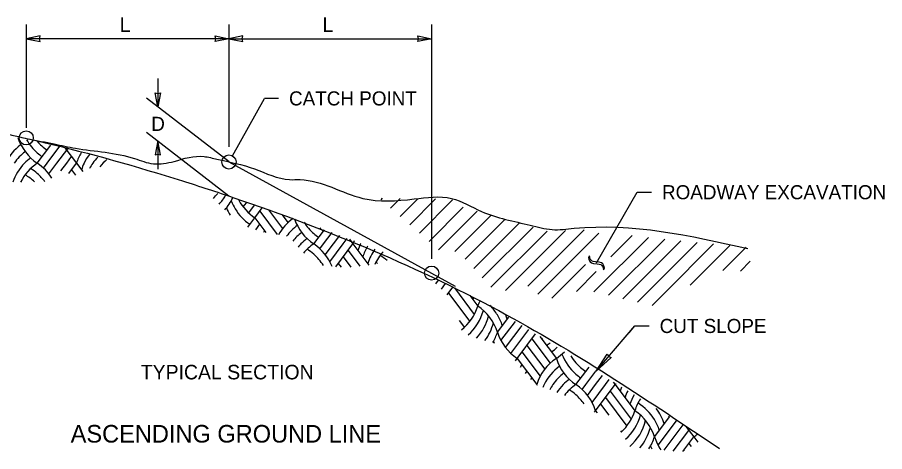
# Model space of a CAD drawing. Extents: x 99862 to 103151, y 100000 to 102076.
# Drawn here: x 100486 to 101470, y 100820 to 101313 of the extents above; entities that cross this region are included whole.
import ezdxf

# ---------------------------------------------------------------- set-up
doc = ezdxf.new("R2010")
doc.units = 0
for name, color, linetype in [('Level 1', 7, 'Continuous'), ('Level 14', 7, 'Continuous'), ('Level 15', 7, 'Continuous'), ('Level 16', 7, 'Continuous'), ('Level 17', 7, 'Continuous'), ('Level 20', 7, 'Continuous'), ('Level 4', 7, 'Continuous')]:
    doc.layers.add(name, color=color, linetype=linetype)

msp = doc.modelspace()

# ---------------------------------------------------------------- linework, layer by layer
at = {"layer": 'Level 1'}
msp.add_spline([(100494.64, 101176.21), (100515.6, 101171.36), (100672.98, 101127.68), (100731.37, 101108.58), (101041.15, 100975.34), (101282.62, 100823.72)], degree=3, dxfattribs=at)
at = {"layer": 'Level 14'}
msp.add_circle((100495.8, 101176.56), 8, dxfattribs=at)
at = {"layer": 'Level 15'}
for p, q in [((100495.8, 101305.14), (100495.8, 101187.96)), ((100725.8, 101305.14), (100725.8, 101166.48)), ((100955.79, 101305.14), (100955.79, 101039.01)), ((100725.8, 101289.14), (100495.8, 101289.14)), ((100725.8, 101289.14), (100955.79, 101289.14)), ((100645.05, 101243.91), (100645.05, 101211.91)), ((100726.14, 101149.17), (100632.39, 101221.7)), ((100729.69, 101156.12), (100766, 101221.34)), ((100782, 101221.34), (100766, 101221.34)), ((100725.8, 101110.52), (100632.39, 101182.78)), ((100645.05, 101172.99), (100645.05, 101140.99)), ((101142.86, 101034.59), (101189.18, 101114.83)), ((101189.19, 101114.83), (101205.19, 101114.83)), ((101142.51, 100911.7), (101186.53, 100962.97)), ((101179.9, 100955.25), (101186.53, 100962.97)), ((101186.53, 100962.97), (101202.53, 100962.97))]:
    msp.add_line(p, q, dxfattribs=at)
for points in [[(100495.8, 101289.14), (100511.53, 101286.05), (100510.8, 101289.14), (100511.53, 101292.22)], [(100725.8, 101289.14), (100710.07, 101286.05), (100710.8, 101289.14), (100710.07, 101292.22)], [(100725.8, 101289.14), (100741.52, 101286.05), (100740.79, 101289.14), (100741.52, 101292.22)], [(100955.79, 101289.14), (100940.07, 101286.05), (100940.8, 101289.14), (100940.07, 101292.22)], [(100645.05, 101211.91), (100641.96, 101227.63), (100645.05, 101226.9), (100648.13, 101227.63)], [(100645.05, 101172.99), (100641.96, 101157.27), (100645.05, 101158), (100648.13, 101157.27)], [(101142.51, 100911.7), (101155.11, 100930.96), (101156.69, 100928.22), (101159.64, 100927.07)]]:
    msp.add_lwpolyline(points, close=True, dxfattribs=at)
for centre in [(100725.8, 101149.14), (100955.79, 101023.01)]:
    msp.add_circle(centre, 8, dxfattribs=at)
at = {"layer": 'Level 16'}
msp.add_line((100725.8, 101149.14), (100982.62, 101008.14), dxfattribs=at)
for points in [[(100081.27, 101269.43), (100433.79, 101190.08), (100494.64, 101176.21)], [(100498.16, 101175.4), (100527.39, 101169.63), (100551.65, 101164.77), (100618.73, 101153.13), (100640.02, 101147.1), (100663.49, 101149.72)], [(100663.49, 101149.72), (100697.52, 101155.38), (100712.23, 101152.2)], [(100712.23, 101152.2), (100754.97, 101141.2), (100794.68, 101129.14), (100806.74, 101129.14), (100877.66, 101107.87), (100935.81, 101107.16), (100978.36, 101107.87), (101012.4, 101092.97), (101067.72, 101077.37), (101092.54, 101072.41), (101117.36, 101073.82), (101314.66, 101050.76)]]:
    msp.add_spline(points, degree=3, dxfattribs=at)
at = {"layer": 'Level 17'}
for p, q in [((100898.35, 101106.27), (100900.03, 101107.95)), ((100909.24, 101096.8), (100920.13, 101107.68)), ((100909.24, 101096.8), (100920.13, 101107.68)), ((100920.14, 101087.33), (100940.23, 101107.42)), ((100931.03, 101077.85), (100960.33, 101107.15)), ((100941.92, 101068.38), (100979.58, 101106.04)), ((100941.92, 101068.38), (100979.58, 101106.04)), ((100952.81, 101058.91), (100991.76, 101097.85)), ((100963.71, 101049.44), (101007.6, 101093.33)), ((100982.29, 101047.66), (101023.44, 101088.8)), ((100982.29, 101047.66), (101023.44, 101088.8)), ((100993.81, 101038.81), (101039.27, 101084.28)), ((101003.52, 101028.16), (101055.11, 101079.75)), ((101013.23, 101017.5), (101070.95, 101075.23)), ((101013.23, 101017.5), (101070.95, 101075.23)), ((101022.94, 101006.84), (101086.79, 101070.7)), ((101039.59, 101003.13), (101107.79, 101071.33)), ((101064.81, 101007.99), (101128.89, 101072.07)), ((101064.81, 101007.99), (101128.89, 101072.07)), ((101076.12, 100998.94), (101145.4, 101068.22)), ((101159.28, 101041.36), (101183.47, 101065.55)), ((101139.96, 101001.68), (101201.71, 101063.43)), ((101156.44, 100997.8), (101220.23, 101061.58)), ((101172.93, 100993.92), (101238.74, 101059.73)), ((101172.93, 100993.92), (101238.74, 101059.73)), ((101189.41, 100990.04), (101257.25, 101057.88)), ((101219.65, 100999.91), (101275.77, 101056.03)), ((101249.22, 101009.12), (101294.28, 101054.18)), ((101266.61, 101026.51), (101294.28, 101054.18)), ((101286.35, 101025.88), (101312.79, 101052.32)), ((101306.09, 101025.26), (101317.22, 101036.39)), ((101092.26, 100994.71), (101130.23, 101032.68)), ((101120.09, 101002.18), (101142.64, 101024.72)), ((101205.9, 100986.16), (101219.5, 100999.76))]:
    msp.add_line(p, q, dxfattribs=at)
at = {"layer": 'Level 20'}
for p, q in [((101134.86, 101042.5), (101133.81, 101040.67)), ((101133.81, 101040.67), (101134.17, 101038.55)), ((101134.17, 101038.55), (101134.81, 101036.9)), ((101134.81, 101036.9), (101135.77, 101035.59)), ((101135.85, 101038.94), (101134.86, 101042.5)), ((101135.77, 101035.59), (101137.09, 101034.59)), ((101136.72, 101037.54), (101135.85, 101038.94)), ((101137.8, 101036.62), (101136.72, 101037.54)), ((101137.09, 101034.59), (101139.39, 101033.7)), ((101139.21, 101036.09), (101137.8, 101036.62)), ((101141.62, 101035.89), (101139.21, 101036.09)), ((101146.02, 101035.51), (101141.62, 101035.89)), ((101148.57, 101034.58), (101146.02, 101035.51)), ((101149.97, 101033.51), (101148.57, 101034.58)), ((101139.39, 101033.7), (101143.47, 101033.43)), ((101143.47, 101033.43), (101146.02, 101033.21)), ((101146.02, 101033.21), (101147.83, 101032.57)), ((101147.83, 101032.57), (101148.88, 101031.75)), ((101148.88, 101031.75), (101149.68, 101030.65)), ((101149.68, 101030.65), (101150.3, 101029.03)), ((101150.99, 101032.14), (101149.97, 101033.51)), ((101150.3, 101029.03), (101150.82, 101026.66)), ((101150.82, 101026.66), (101151.88, 101028.49)), ((101151.62, 101030.47), (101150.99, 101032.14)), ((101151.88, 101028.49), (101151.62, 101030.47))]:
    msp.add_line(p, q, dxfattribs=at)
at = {"layer": 'Level 4'}
for p, q in [((100508.31, 101147.82), (100523.75, 101168.4)), ((100519.44, 101147.82), (100533.78, 101166.93)), ((100530.58, 101147.82), (100542.88, 101164.22)), ((100539.75, 101165.29), (100552.86, 101147.82)), ((100541.72, 101147.82), (100547.29, 101155.24)), ((100515.29, 101142.28), (100519.44, 101147.82)), ((100521.4, 101135.58), (100530.58, 101147.82)), ((100535.15, 101139.06), (100541.72, 101147.82)), ((100544.06, 101136.09), (100552.86, 101147.82)), ((100552.86, 101147.82), (100560.06, 101138.22)), ((100547.29, 101140.39), (100551.85, 101134.31)), ((100742.09, 101098.05), (100745.56, 101102.69)), ((100748.2, 101091.36), (100754.77, 101100.11)), ((100755.19, 101085.82), (100763.52, 101096.93)), ((100770.84, 101094.65), (100786.64, 101073.58)), ((100747.15, 101075.1), (100755.19, 101085.82)), ((100755.19, 101085.82), (100767.76, 101069.05)), ((100760.75, 101093.24), (100780.59, 101066.79)), ((100786.19, 101089.02), (100792.75, 101080.28)), ((100756.17, 101072.28), (100760.75, 101078.39)), ((100765.22, 101069.5), (100766.32, 101070.97)), ((100822.01, 101056.12), (100834.11, 101072.26)), ((100833.14, 101056.12), (100842.84, 101069.05)), ((100844.28, 101056.12), (100851.5, 101065.75)), ((100828.99, 101050.58), (100833.14, 101056.12)), ((100835.1, 101043.88), (100844.28, 101056.12)), ((100840.27, 101035.92), (100855.42, 101056.12)), ((100847.11, 101030.19), (100866.55, 101056.12)), ((100855.42, 101056.12), (100860.13, 101062.4)), ((100862.55, 101061.46), (100866.55, 101056.12)), ((100866.55, 101056.12), (100884.68, 101031.96)), ((100860.99, 101048.69), (100874.32, 101030.92)), ((100855.42, 101041.27), (100863.96, 101029.88)), ((100849.85, 101033.84), (100853.01, 101029.63)), ((100960.38, 101010.82), (100963.5, 101014.97)), ((100966.89, 101004.65), (100971.65, 101010.99)), ((100973.39, 100998.47), (100979.8, 101007.01)), ((100981.6, 101006.13), (101004.2, 100976)), ((100974.8, 101000.35), (100999.03, 100968.04)), ((100999.17, 100997.55), (101008.21, 100985.5)), ((100987.07, 100969.14), (100992.92, 100961.34)), ((101030.48, 100955.8), (101043.33, 100972.94)), ((101034.5, 100946.3), (101050.93, 100968.22)), ((101039.66, 100938.34), (101058.53, 100963.5)), ((101045.78, 100931.64), (101066.13, 100958.78)), ((101052.76, 100926.1), (101073.72, 100954.06)), ((101069.46, 100948.38), (101090.32, 100920.56)), ((101078.62, 100951.01), (101097.31, 100926.1)), ((101063.89, 100940.95), (101084.21, 100913.87)), ((101058.33, 100933.53), (101079.04, 100905.91)), ((101050.78, 100923.46), (101052.76, 100926.1)), ((101052.76, 100926.1), (101075.03, 100896.41)), ((101056.5, 100916.25), (101058.33, 100918.68)), ((101062.22, 100909.03), (101063.89, 100911.25)), ((101119.58, 100896.41), (101134.5, 100916.31)), ((101130.71, 100896.41), (101142.11, 100911.6)), ((101141.85, 100896.41), (101149.72, 100906.89)), ((101068.24, 100902.2), (101069.46, 100903.83)), ((101152.99, 100896.41), (101157.32, 100902.18)), ((101161.94, 100899.32), (101164.13, 100896.41)), ((101074.74, 100896.02), (101075.03, 100896.41)), ((101075.03, 100896.41), (101075.56, 100895.71)), ((101126.56, 100890.86), (101130.71, 100896.41)), ((101132.67, 100884.17), (101141.85, 100896.41)), ((101137.84, 100876.21), (101152.99, 100896.41)), ((101141.85, 100866.71), (101164.13, 100896.41)), ((101158.56, 100888.98), (101182.39, 100857.21)), ((101164.13, 100896.41), (101186.4, 100866.71)), ((101152.99, 100881.56), (101177.22, 100849.24)), ((101147.42, 100874.13), (101156.71, 100861.74)), ((101140.55, 100864.97), (101141.85, 100866.71)), ((101141.85, 100866.71), (101143.61, 100864.36)), ((101208.67, 100837.01), (101225.94, 100860.03)), ((101212.68, 100827.51), (101233.6, 100855.4)), ((101219.61, 100821.89), (101241.26, 100850.76)), ((101244.27, 100848.94), (101253.22, 100837.01)), ((101170.08, 100843.92), (101171.11, 100842.55)), ((101229.95, 100820.84), (101247.65, 100844.43)), ((101240.65, 100820.24), (101253.22, 100837.01)), ((101247.65, 100829.58), (101250.21, 100826.18)), ((101253.22, 100837.01), (101257.81, 100830.89)), ((101242.08, 100822.16), (101242.61, 100821.46))]:
    msp.add_line(p, q, dxfattribs=at)
for centre, start, end in [((100539.75, 101194.6), 198.22662, 236.09639), ((100539.75, 101194.6), 202.24668, 203.08162), ((100545.32, 101202.02), 209.35448, 228.95992), ((100550.89, 101209.45), 220.5204, 236.09639), ((100523.04, 101123.31), 126.71786, 154.2266), ((100528.61, 101115.88), 127.1006, 145.49109), ((100534.18, 101108.46), 126.331, 135.71278), ((100545.32, 101202.02), 228.95986, 236.09639), ((100606.57, 101130.73), 149.28802, 162.3566), ((100612.14, 101123.31), 141.90599, 154.2266), ((100617.71, 101115.88), 136.41204, 145.49109), ((100534.18, 101108.46), 135.71269, 161.79649), ((100539.75, 101101.03), 123.90361, 153.45584), ((100476.87, 101101.03), 31.64966, 56.09634), ((100612.14, 101123.31), 154.22654, 162.3566), ((100617.71, 101115.88), 145.49102, 152.80365), ((100623.28, 101108.46), 129.59897, 141.21541), ((100623.28, 101108.46), 134.50839, 135.71278), ((100465.73, 101086.18), 45.67354, 59.30215), ((100471.3, 101093.61), 48.95968, 58.54646), ((100471.3, 101093.61), 35.97372, 48.95975), ((100460.16, 101078.76), 57.39834, 58.48737), ((100668.06, 101147.45), 315.29494, 323.03736), ((100673.63, 101140.02), 316.62931, 328.95774), ((100679.2, 101132.6), 317.96456, 334.509), ((100781.06, 101125.18), 201.08053, 211.33197), ((100786.63, 101132.6), 208.28144, 236.09639), ((100775.49, 101117.75), 201.43438, 210.92517), ((100781.06, 101125.18), 211.33188, 236.09639), ((100831.17, 101039.03), 125.39128, 150.78643), ((100853.45, 101102.9), 199.11695, 236.09639), ((100836.74, 101031.61), 126.30625, 143.79192), ((100859.02, 101110.33), 211.65684, 228.95992), ((100864.58, 101117.75), 230.55849, 236.09639), ((100842.31, 101024.19), 127.1006, 141.55728), ((100859.02, 101110.33), 228.95986, 236.09639), ((100847.88, 101016.76), 135.71269, 140.73228), ((100847.88, 101016.76), 126.331, 135.71278), ((100853.45, 101009.34), 123.90361, 139.90917), ((100790.57, 101009.34), 22.16876, 56.09634), ((100920.27, 101039.03), 158.77108, 162.3566), ((100925.84, 101031.61), 154.22654, 162.3566), ((100925.84, 101031.61), 153.78062, 154.2266), ((100785, 101001.91), 48.95968, 58.54646), ((100785, 101001.91), 31.71162, 48.95975), ((100931.41, 101024.19), 148.7928, 162.3566), ((100936.97, 101016.76), 143.76994, 162.3566), ((100942.54, 101009.34), 137.86379, 155.53104), ((100862.96, 100987.06), 55.96323, 58.48737), ((100868.52, 100994.49), 49.46126, 59.30215), ((101056.36, 100975.84), 159.6592, 162.3566), ((100954.5, 101002.58), 308.66812, 342.3566), ((101061.93, 100968.42), 155.35238, 162.3566), ((100976.77, 100938.72), 17.6434, 56.09639), ((100982.34, 100946.14), 31.33163, 45.2572), ((100960.06, 100995.16), 311.2525, 345.01126), ((100965.63, 100987.74), 316.68997, 346.31988), ((100971.2, 100980.31), 323.07667, 345.77133), ((100982.34, 100946.14), 17.6434, 31.33172), ((100987.91, 100953.57), 17.6434, 22.32309), ((100976.77, 100972.89), 329.19097, 342.3566), ((101084.2, 100972.89), 197.64354, 236.09639), ((101049.16, 100995.16), 303.90361, 305.22995), ((101078.63, 100965.46), 200.87781, 202.80971), ((101054.73, 100987.74), 303.90361, 308.90024), ((101060.3, 100980.31), 303.90361, 312.49006), ((101065.86, 100972.89), 303.90361, 316.01781), ((101156.59, 100950.61), 200.24322, 228.95992), ((101162.16, 100958.04), 210.75745, 220.94161), ((101128.75, 100879.32), 123.90361, 162.3566), ((101134.31, 100871.9), 126.30625, 154.2266), ((101151.02, 100943.19), 197.6434, 236.09639), ((101162.16, 100958.04), 220.94154, 236.09639), ((101139.88, 100864.47), 127.1006, 145.49109), ((101156.59, 100950.61), 228.95986, 236.09639), ((101145.45, 100857.05), 126.331, 135.71278), ((101217.84, 100879.32), 160.96688, 162.3566), ((101134.31, 100871.9), 154.22654, 157.77539), ((101139.88, 100864.47), 145.49102, 152.70564), ((101145.45, 100857.05), 135.71269, 147.58353), ((101151.02, 100849.62), 123.90361, 142.36453), ((101082.57, 100842.2), 48.95968, 58.54646), ((101088.14, 100849.62), 17.6434, 56.09634), ((101223.41, 100871.9), 157.46454, 162.3566), ((101228.98, 100864.47), 153.99674, 162.3566), ((101082.57, 100842.2), 35.01638, 48.95975), ((101234.55, 100857.05), 150.55, 162.3566), ((101240.11, 100849.62), 147.11162, 162.3566), ((101160.53, 100827.35), 31.33163, 58.48737), ((101166.09, 100834.77), 17.6434, 37.74808), ((101132.68, 100883.79), 312.77805, 342.3566), ((101138.25, 100876.37), 311.72252, 345.01126), ((101154.96, 100819.92), 17.6434, 56.09639), ((101171.66, 100842.2), 17.6434, 19.10782), ((101143.82, 100868.94), 310.67081, 346.31988), ((101149.39, 100861.52), 319.22295, 345.77133), ((101160.53, 100827.35), 17.6434, 31.33172), ((101221.78, 100883.79), 303.90361, 310.01012), ((101154.96, 100854.09), 327.31062, 342.3566), ((101262.39, 100854.09), 197.64354, 214.36438), ((101256.82, 100846.67), 200.87781, 204.45637)]:
    msp.add_arc(centre, 56.37, start, end, dxfattribs=at)

# ---------------------------------------------------------------- texts
at = {"layer": 'Level 15'}
msp.add_text('D', height=16, dxfattribs=at).set_placement((100637.65, 101184.45))
at = {"layer": 'Level 20'}
for s, height, p in [('L ', 16.5, (100601.88, 101296.89)), ('L ', 16.5, (100831.88, 101296.89)), ('CATCH POINT', 16, (100794, 101213.34)), ('ROADWAY EXCAVATION', 16, (101217.19, 101106.83)), ('CUT SLOPE', 16, (101214.53, 100954.97)), ('TYPICAL SECTION', 16.5, (100625.71, 100902.32)), ('ASCENDING GROUND LINE', 20, (100546.19, 100830.57))]:
    msp.add_text(s, height=height, dxfattribs=at).set_placement(p)

doc.saveas('drawing.dxf')
